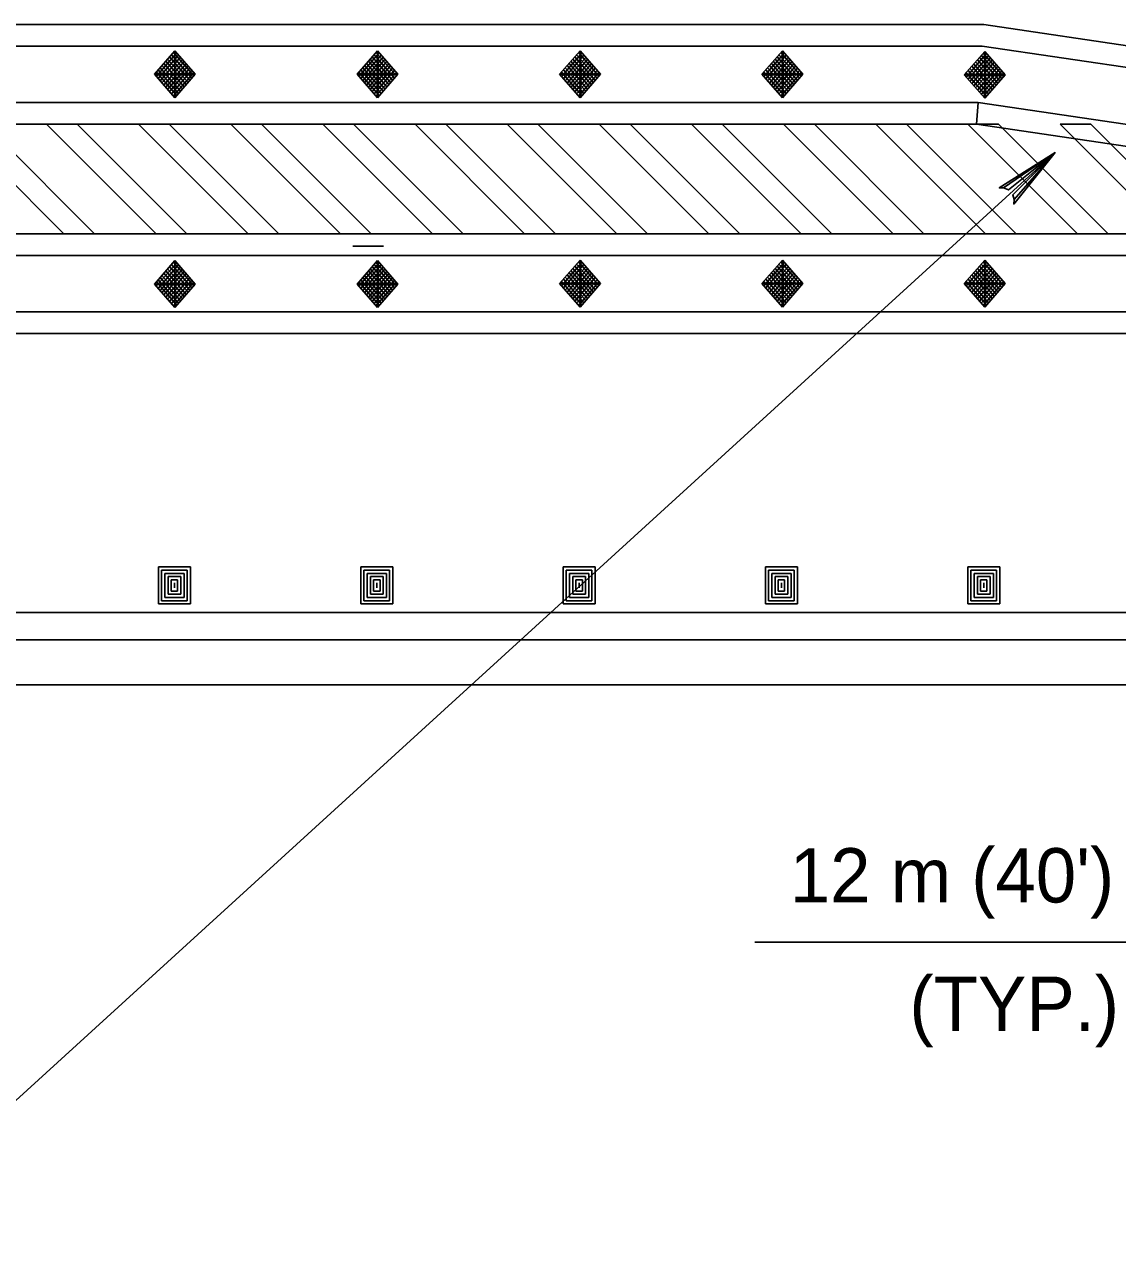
# Model space of a CAD drawing. Extents: x 639362 to 641108, y 298458 to 299646.
# Drawn here: x 639666.7 to 639727.1, y 298704.6 to 298772.2 of the extents above; entities that cross this region are included whole.
import ezdxf

# ---------------------------------------------------------------- set-up
doc = ezdxf.new("R2010")
doc.units = 0
doc.layers.add('2', color=7, linetype='Continuous')
doc.layers.add('3', color=7, linetype='Continuous')

# ---------------------------------------------------------------- blocks, each defined once
blk = doc.blocks.new('RARROW')
at = {"layer": '3'}
blk.add_lwpolyline([(-2.2695, 0.285), (-2.184875, 0.12075), (0, 0), (-2.2695, 0.285), (-2.38575, 0.384625), (0, 0), (-2.183125, -0.108), (-2.262875, -0.2705), (0, 0), (-2.38575, -0.379125), (-2.262875, -0.2705)], dxfattribs=at)

msp = doc.modelspace()

# ---------------------------------------------------------------- linework, layer by layer
at = {"layer": '2'}
for p, q in [((639719.726, 298772.157), (639431.255, 298772.157)), ((639797.996, 298760.59), (639719.726, 298772.157)), ((639431.255, 298770.957), (639719.637, 298770.957)), ((639675.014, 298770.702), (639673.887, 298769.407)), ((639675.119, 298770.582), (639674.005, 298769.303)), ((639675.223, 298770.462), (639674.095, 298769.167)), ((639674.826, 298770.486), (639675.954, 298769.191)), ((639674.931, 298770.606), (639676.058, 298769.311)), ((639676.142, 298769.407), (639675.014, 298770.702)), ((639675.014, 298770.702), (639675.014, 298768.111)), ((639686.213, 298770.702), (639685.085, 298769.407)), ((639686.317, 298770.582), (639685.204, 298769.303)), ((639686.421, 298770.462), (639685.294, 298769.167)), ((639686.025, 298770.486), (639687.152, 298769.191)), ((639686.129, 298770.606), (639687.257, 298769.311)), ((639687.34, 298769.407), (639686.213, 298770.702)), ((639686.213, 298770.702), (639686.213, 298768.111)), ((639697.412, 298770.696), (639696.284, 298769.401)), ((639697.516, 298770.576), (639696.403, 298769.298)), ((639697.224, 298770.48), (639698.351, 298769.185)), ((639697.328, 298770.6), (639698.456, 298769.305)), ((639698.539, 298769.401), (639697.412, 298770.696)), ((639697.412, 298770.696), (639697.412, 298768.106)), ((639708.595, 298770.696), (639707.468, 298769.401)), ((639708.7, 298770.576), (639707.587, 298769.298)), ((639708.408, 298770.48), (639709.535, 298769.185)), ((639708.512, 298770.6), (639709.639, 298769.305)), ((639709.723, 298769.401), (639708.595, 298770.696)), ((639708.595, 298770.696), (639708.595, 298768.106)), ((639719.779, 298770.666), (639718.652, 298769.371)), ((639719.884, 298770.547), (639718.77, 298769.268)), ((639719.637, 298770.957), (639797.908, 298759.39)), ((639719.696, 298770.57), (639720.823, 298769.275)), ((639720.907, 298769.371), (639719.779, 298770.666)), ((639719.779, 298770.666), (639719.779, 298768.076)), ((639675.327, 298770.342), (639674.2, 298769.047)), ((639675.432, 298770.223), (639674.304, 298768.927)), ((639674.304, 298769.887), (639675.432, 298768.591)), ((639675.536, 298770.103), (639674.409, 298768.807)), ((639674.409, 298770.007), (639675.536, 298768.711)), ((639674.513, 298770.127), (639675.641, 298768.831)), ((639675.641, 298769.983), (639674.513, 298768.687)), ((639674.617, 298770.247), (639675.745, 298768.951)), ((639675.745, 298769.863), (639674.617, 298768.567)), ((639674.722, 298770.366), (639675.849, 298769.071)), ((639686.526, 298770.342), (639685.398, 298769.047)), ((639686.63, 298770.223), (639685.503, 298768.927)), ((639685.503, 298769.887), (639686.63, 298768.591)), ((639686.735, 298770.103), (639685.607, 298768.807)), ((639685.607, 298770.007), (639686.735, 298768.711)), ((639685.711, 298770.127), (639686.839, 298768.831)), ((639686.839, 298769.983), (639685.711, 298768.687)), ((639685.816, 298770.247), (639686.943, 298768.951)), ((639686.943, 298769.863), (639685.816, 298768.567)), ((639685.92, 298770.366), (639687.048, 298769.071)), ((639697.621, 298770.456), (639696.493, 298769.161)), ((639697.725, 298770.337), (639696.597, 298769.041)), ((639697.829, 298770.217), (639696.702, 298768.921)), ((639696.702, 298769.881), (639697.829, 298768.585)), ((639697.934, 298770.097), (639696.806, 298768.801)), ((639696.806, 298770.001), (639697.934, 298768.705)), ((639696.911, 298770.121), (639698.038, 298768.825)), ((639698.038, 298769.977), (639696.911, 298768.681)), ((639697.015, 298770.241), (639698.143, 298768.945)), ((639698.143, 298769.857), (639697.015, 298768.561)), ((639697.119, 298770.361), (639698.247, 298769.065)), ((639708.804, 298770.456), (639707.677, 298769.161)), ((639708.909, 298770.337), (639707.781, 298769.041)), ((639709.013, 298770.217), (639707.885, 298768.921)), ((639707.885, 298769.881), (639709.013, 298768.585)), ((639709.117, 298770.097), (639707.99, 298768.801)), ((639707.99, 298770.001), (639709.117, 298768.705)), ((639708.094, 298770.121), (639709.222, 298768.825)), ((639709.222, 298769.977), (639708.094, 298768.681)), ((639708.199, 298770.241), (639709.326, 298768.945)), ((639709.326, 298769.857), (639708.199, 298768.561)), ((639708.303, 298770.361), (639709.431, 298769.065)), ((639719.988, 298770.427), (639718.86, 298769.131)), ((639720.092, 298770.307), (639718.965, 298769.011)), ((639720.197, 298770.187), (639719.069, 298768.891)), ((639719.069, 298769.851), (639720.197, 298768.555)), ((639720.301, 298770.067), (639719.174, 298768.771)), ((639719.174, 298769.971), (639720.301, 298768.675)), ((639719.278, 298770.091), (639720.406, 298768.795)), ((639720.406, 298769.947), (639719.278, 298768.651)), ((639719.382, 298770.211), (639720.51, 298768.915)), ((639720.51, 298769.827), (639719.382, 298768.531)), ((639719.487, 298770.331), (639720.614, 298769.035)), ((639719.591, 298770.451), (639720.719, 298769.155)), ((639673.887, 298769.407), (639675.014, 298768.111)), ((639673.887, 298769.407), (639676.142, 298769.407)), ((639673.991, 298769.527), (639675.119, 298768.231)), ((639674.095, 298769.647), (639675.223, 298768.351)), ((639674.2, 298769.767), (639675.327, 298768.471)), ((639675.849, 298769.743), (639674.722, 298768.447)), ((639675.954, 298769.623), (639674.826, 298768.327)), ((639676.058, 298769.503), (639674.931, 298768.207)), ((639675.014, 298768.111), (639676.142, 298769.407)), ((639685.085, 298769.407), (639686.213, 298768.111)), ((639685.085, 298769.407), (639687.34, 298769.407)), ((639685.189, 298769.527), (639686.317, 298768.231)), ((639685.294, 298769.647), (639686.421, 298768.351)), ((639685.398, 298769.767), (639686.526, 298768.471)), ((639687.048, 298769.743), (639685.92, 298768.447)), ((639687.152, 298769.623), (639686.025, 298768.327)), ((639687.257, 298769.503), (639686.129, 298768.207)), ((639686.213, 298768.111), (639687.34, 298769.407)), ((639696.284, 298769.401), (639697.412, 298768.106)), ((639696.284, 298769.401), (639698.539, 298769.401)), ((639696.389, 298769.521), (639697.516, 298768.225)), ((639696.493, 298769.641), (639697.621, 298768.345)), ((639696.597, 298769.761), (639697.725, 298768.465)), ((639698.247, 298769.737), (639697.119, 298768.441)), ((639698.351, 298769.617), (639697.224, 298768.321)), ((639698.456, 298769.497), (639697.328, 298768.201)), ((639697.412, 298768.106), (639698.539, 298769.401)), ((639707.468, 298769.401), (639708.595, 298768.106)), ((639707.468, 298769.401), (639709.723, 298769.401)), ((639707.572, 298769.521), (639708.7, 298768.225)), ((639707.677, 298769.641), (639708.804, 298768.345)), ((639707.781, 298769.761), (639708.909, 298768.465)), ((639709.431, 298769.737), (639708.303, 298768.441)), ((639709.535, 298769.617), (639708.408, 298768.321)), ((639709.639, 298769.497), (639708.512, 298768.201)), ((639708.595, 298768.106), (639709.723, 298769.401)), ((639718.652, 298769.371), (639719.779, 298768.076)), ((639718.652, 298769.371), (639720.907, 298769.371)), ((639718.756, 298769.491), (639719.884, 298768.196)), ((639718.86, 298769.611), (639719.988, 298768.315)), ((639718.965, 298769.731), (639720.092, 298768.435)), ((639720.614, 298769.707), (639719.487, 298768.411)), ((639720.719, 298769.587), (639719.591, 298768.292)), ((639720.823, 298769.467), (639719.696, 298768.172)), ((639719.779, 298768.076), (639720.907, 298769.371)), ((639719.409, 298767.845), (639606.893, 298767.845)), ((639719.409, 298767.845), (639719.32, 298766.645)), ((639719.32, 298766.645), (639719.409, 298767.845)), ((639776.623, 298759.39), (639719.409, 298767.845)), ((639623.223, 298766.645), (639719.32, 298766.645)), ((639668.883, 298760.59), (639662.822, 298766.645)), ((639664.52, 298766.645), (639670.58, 298760.59)), ((639673.976, 298760.59), (639667.916, 298766.645)), ((639667.916, 298766.645), (639669.614, 298766.645)), ((639669.614, 298766.645), (639675.674, 298760.59)), ((639679.07, 298760.59), (639673.009, 298766.645)), ((639673.009, 298766.645), (639674.707, 298766.645)), ((639674.707, 298766.645), (639680.767, 298760.59)), ((639684.163, 298760.59), (639678.103, 298766.645)), ((639678.103, 298766.645), (639679.801, 298766.645)), ((639679.801, 298766.645), (639685.861, 298760.59)), ((639689.257, 298760.59), (639683.196, 298766.645)), ((639683.196, 298766.645), (639684.894, 298766.645)), ((639684.894, 298766.645), (639690.954, 298760.59)), ((639694.35, 298760.59), (639688.29, 298766.645)), ((639688.29, 298766.645), (639689.988, 298766.645)), ((639689.988, 298766.645), (639696.048, 298760.59)), ((639699.444, 298760.59), (639693.383, 298766.645)), ((639693.383, 298766.645), (639695.081, 298766.645)), ((639695.081, 298766.645), (639701.141, 298760.59)), ((639704.537, 298760.59), (639698.477, 298766.645)), ((639698.477, 298766.645), (639700.175, 298766.645)), ((639700.175, 298766.645), (639706.235, 298760.59)), ((639709.631, 298760.59), (639703.57, 298766.645)), ((639703.57, 298766.645), (639705.268, 298766.645)), ((639705.268, 298766.645), (639711.328, 298760.59)), ((639714.724, 298760.59), (639708.664, 298766.645)), ((639708.664, 298766.645), (639710.362, 298766.645)), ((639710.362, 298766.645), (639716.422, 298760.59)), ((639719.818, 298760.59), (639713.757, 298766.645)), ((639713.757, 298766.645), (639715.455, 298766.645)), ((639715.455, 298766.645), (639721.515, 298760.59)), ((639724.911, 298760.59), (639718.851, 298766.645)), ((639718.851, 298766.645), (639720.549, 298766.645)), ((639719.32, 298766.645), (639760.294, 298760.59)), ((639720.549, 298766.645), (639726.609, 298760.59)), ((639730.005, 298760.59), (639723.944, 298766.645)), ((639723.944, 298766.645), (639725.642, 298766.645)), ((639725.642, 298766.645), (639731.702, 298760.59)), ((639657.3, 298704.573), (639723.666, 298765.08)), ((639760.294, 298760.59), (639664.196, 298760.59)), ((639670.58, 298760.59), (639668.883, 298760.59)), ((639675.674, 298760.59), (639673.976, 298760.59)), ((639680.767, 298760.59), (639679.07, 298760.59)), ((639685.861, 298760.59), (639684.163, 298760.59)), ((639690.954, 298760.59), (639689.257, 298760.59)), ((639696.048, 298760.59), (639694.35, 298760.59)), ((639701.141, 298760.59), (639699.444, 298760.59)), ((639706.235, 298760.59), (639704.537, 298760.59)), ((639711.328, 298760.59), (639709.631, 298760.59)), ((639716.422, 298760.59), (639714.724, 298760.59)), ((639721.515, 298760.59), (639719.818, 298760.59)), ((639726.609, 298760.59), (639724.911, 298760.59)), ((639686.547, 298759.905), (639684.849, 298759.905)), ((639664.108, 298759.39), (639776.623, 298759.39)), ((639675.014, 298759.11), (639673.887, 298757.814)), ((639675.119, 298758.99), (639674.005, 298757.711)), ((639674.931, 298759.014), (639676.058, 298757.718)), ((639676.142, 298757.814), (639675.014, 298759.11)), ((639675.014, 298759.11), (639675.014, 298756.519)), ((639686.213, 298759.11), (639685.085, 298757.814)), ((639686.317, 298758.99), (639685.204, 298757.711)), ((639686.129, 298759.014), (639687.257, 298757.718)), ((639687.34, 298757.814), (639686.213, 298759.11)), ((639686.213, 298759.11), (639686.213, 298756.519)), ((639697.412, 298759.13), (639696.284, 298757.835)), ((639697.516, 298759.01), (639696.403, 298757.731)), ((639697.328, 298759.034), (639698.456, 298757.739)), ((639698.539, 298757.835), (639697.412, 298759.13)), ((639697.412, 298759.13), (639697.412, 298756.539)), ((639708.595, 298759.13), (639707.468, 298757.835)), ((639708.7, 298759.01), (639707.587, 298757.731)), ((639708.512, 298759.034), (639709.639, 298757.739)), ((639709.723, 298757.835), (639708.595, 298759.13)), ((639708.595, 298759.13), (639708.595, 298756.539)), ((639719.779, 298759.13), (639718.652, 298757.835)), ((639719.884, 298759.01), (639718.77, 298757.731)), ((639719.696, 298759.034), (639720.823, 298757.739)), ((639720.907, 298757.835), (639719.779, 298759.13)), ((639719.779, 298759.13), (639719.779, 298756.539)), ((639675.223, 298758.87), (639674.095, 298757.574)), ((639675.327, 298758.75), (639674.2, 298757.454)), ((639675.432, 298758.63), (639674.304, 298757.335)), ((639674.304, 298758.294), (639675.432, 298756.999)), ((639675.536, 298758.51), (639674.409, 298757.215)), ((639674.409, 298758.414), (639675.536, 298757.119)), ((639674.513, 298758.534), (639675.641, 298757.239)), ((639675.641, 298758.39), (639674.513, 298757.095)), ((639674.617, 298758.654), (639675.745, 298757.359)), ((639674.722, 298758.774), (639675.849, 298757.478)), ((639674.826, 298758.894), (639675.954, 298757.598)), ((639686.421, 298758.87), (639685.294, 298757.574)), ((639686.526, 298758.75), (639685.398, 298757.454)), ((639686.63, 298758.63), (639685.503, 298757.335)), ((639685.503, 298758.294), (639686.63, 298756.999)), ((639686.735, 298758.51), (639685.607, 298757.215)), ((639685.607, 298758.414), (639686.735, 298757.119)), ((639685.711, 298758.534), (639686.839, 298757.239)), ((639686.839, 298758.39), (639685.711, 298757.095)), ((639685.816, 298758.654), (639686.943, 298757.359)), ((639685.92, 298758.774), (639687.048, 298757.478)), ((639686.025, 298758.894), (639687.152, 298757.598)), ((639697.621, 298758.89), (639696.493, 298757.595)), ((639697.725, 298758.77), (639696.597, 298757.475)), ((639697.829, 298758.65), (639696.702, 298757.355)), ((639696.702, 298758.314), (639697.829, 298757.019)), ((639697.934, 298758.53), (639696.806, 298757.235)), ((639696.806, 298758.434), (639697.934, 298757.139)), ((639696.911, 298758.554), (639698.038, 298757.259)), ((639698.038, 298758.41), (639696.911, 298757.115)), ((639697.015, 298758.674), (639698.143, 298757.379)), ((639697.119, 298758.794), (639698.247, 298757.499)), ((639697.224, 298758.914), (639698.351, 298757.619)), ((639708.804, 298758.89), (639707.677, 298757.595)), ((639708.909, 298758.77), (639707.781, 298757.475)), ((639709.013, 298758.65), (639707.885, 298757.355)), ((639707.885, 298758.314), (639709.013, 298757.019)), ((639709.117, 298758.53), (639707.99, 298757.235)), ((639707.99, 298758.434), (639709.117, 298757.139)), ((639708.094, 298758.554), (639709.222, 298757.259)), ((639709.222, 298758.41), (639708.094, 298757.115)), ((639708.199, 298758.674), (639709.326, 298757.379)), ((639708.303, 298758.794), (639709.431, 298757.499)), ((639708.408, 298758.914), (639709.535, 298757.619)), ((639719.988, 298758.89), (639718.86, 298757.595)), ((639720.092, 298758.77), (639718.965, 298757.475)), ((639720.197, 298758.65), (639719.069, 298757.355)), ((639719.069, 298758.314), (639720.197, 298757.019)), ((639720.301, 298758.53), (639719.174, 298757.235)), ((639719.174, 298758.434), (639720.301, 298757.139)), ((639719.278, 298758.554), (639720.406, 298757.259)), ((639720.406, 298758.41), (639719.278, 298757.115)), ((639719.382, 298758.674), (639720.51, 298757.379)), ((639719.487, 298758.794), (639720.614, 298757.499)), ((639719.591, 298758.914), (639720.719, 298757.619)), ((639673.887, 298757.814), (639675.014, 298756.519)), ((639673.887, 298757.814), (639676.142, 298757.814)), ((639673.991, 298757.934), (639675.119, 298756.639)), ((639674.095, 298758.054), (639675.223, 298756.759)), ((639674.2, 298758.174), (639675.327, 298756.879)), ((639675.745, 298758.27), (639674.617, 298756.975)), ((639675.849, 298758.15), (639674.722, 298756.855)), ((639675.954, 298758.03), (639674.826, 298756.735)), ((639676.058, 298757.91), (639674.931, 298756.615)), ((639675.014, 298756.519), (639676.142, 298757.814)), ((639685.085, 298757.814), (639686.213, 298756.519)), ((639685.085, 298757.814), (639687.34, 298757.814)), ((639685.189, 298757.934), (639686.317, 298756.639)), ((639685.294, 298758.054), (639686.421, 298756.759)), ((639685.398, 298758.174), (639686.526, 298756.879)), ((639686.943, 298758.27), (639685.816, 298756.975)), ((639687.048, 298758.15), (639685.92, 298756.855)), ((639687.152, 298758.03), (639686.025, 298756.735)), ((639687.257, 298757.91), (639686.129, 298756.615)), ((639686.213, 298756.519), (639687.34, 298757.814)), ((639696.284, 298757.835), (639697.412, 298756.539)), ((639696.284, 298757.835), (639698.539, 298757.835)), ((639696.389, 298757.955), (639697.516, 298756.659)), ((639696.493, 298758.075), (639697.621, 298756.779)), ((639696.597, 298758.194), (639697.725, 298756.899)), ((639698.143, 298758.29), (639697.015, 298756.995)), ((639698.247, 298758.17), (639697.119, 298756.875)), ((639698.351, 298758.051), (639697.224, 298756.755)), ((639698.456, 298757.931), (639697.328, 298756.635)), ((639697.412, 298756.539), (639698.539, 298757.835)), ((639707.468, 298757.835), (639708.595, 298756.539)), ((639707.468, 298757.835), (639709.723, 298757.835)), ((639707.572, 298757.955), (639708.7, 298756.659)), ((639707.677, 298758.075), (639708.804, 298756.779)), ((639707.781, 298758.194), (639708.909, 298756.899)), ((639709.326, 298758.29), (639708.199, 298756.995)), ((639709.431, 298758.17), (639708.303, 298756.875)), ((639709.535, 298758.051), (639708.408, 298756.755)), ((639709.639, 298757.931), (639708.512, 298756.635)), ((639708.595, 298756.539), (639709.723, 298757.835)), ((639718.652, 298757.835), (639719.779, 298756.539)), ((639718.652, 298757.835), (639720.907, 298757.835)), ((639718.756, 298757.955), (639719.884, 298756.659)), ((639718.86, 298758.075), (639719.988, 298756.779)), ((639718.965, 298758.194), (639720.092, 298756.899)), ((639720.51, 298758.29), (639719.382, 298756.995)), ((639720.614, 298758.17), (639719.487, 298756.875)), ((639720.719, 298758.051), (639719.591, 298756.755)), ((639720.823, 298757.931), (639719.696, 298756.635)), ((639719.779, 298756.539), (639720.907, 298757.835)), ((639663.879, 298756.279), (639952.262, 298756.279)), ((639952.262, 298755.079), (639663.791, 298755.079)), ((639674.106, 298742.179), (639675.881, 298742.179)), ((639674.106, 298740.14), (639674.106, 298742.179)), ((639675.881, 298742.179), (639675.881, 298740.14)), ((639685.289, 298742.179), (639687.064, 298742.179)), ((639685.289, 298740.14), (639685.289, 298742.179)), ((639687.064, 298742.179), (639687.064, 298740.14)), ((639696.473, 298742.179), (639698.248, 298742.179)), ((639696.473, 298740.14), (639696.473, 298742.179)), ((639698.248, 298742.179), (639698.248, 298740.14)), ((639707.657, 298742.179), (639709.432, 298742.179)), ((639707.657, 298740.14), (639707.657, 298742.179)), ((639709.432, 298742.179), (639709.432, 298740.14)), ((639718.841, 298742.179), (639720.616, 298742.179)), ((639718.841, 298740.14), (639718.841, 298742.179)), ((639720.616, 298742.179), (639720.616, 298740.14)), ((639674.283, 298742.001), (639675.702, 298742.001)), ((639674.283, 298740.317), (639674.283, 298742.001)), ((639674.461, 298741.824), (639675.525, 298741.824)), ((639674.461, 298740.495), (639674.461, 298741.824)), ((639674.638, 298740.672), (639674.638, 298741.647)), ((639674.638, 298741.647), (639675.347, 298741.647)), ((639674.816, 298741.471), (639675.17, 298741.471)), ((639674.816, 298740.849), (639674.816, 298741.471)), ((639675.17, 298741.471), (639675.17, 298740.849)), ((639675.347, 298741.647), (639675.347, 298740.672)), ((639675.525, 298741.824), (639675.525, 298740.495)), ((639675.702, 298742.001), (639675.702, 298740.317)), ((639685.466, 298742.001), (639686.886, 298742.001)), ((639685.466, 298740.317), (639685.466, 298742.001)), ((639685.645, 298741.824), (639686.709, 298741.824)), ((639685.645, 298740.495), (639685.645, 298741.824)), ((639685.822, 298740.672), (639685.822, 298741.647)), ((639685.822, 298741.647), (639686.531, 298741.647)), ((639686, 298741.471), (639686.354, 298741.471)), ((639686, 298740.849), (639686, 298741.471)), ((639686.354, 298741.471), (639686.354, 298740.849)), ((639686.531, 298741.647), (639686.531, 298740.672)), ((639686.709, 298741.824), (639686.709, 298740.495)), ((639686.886, 298742.001), (639686.886, 298740.317)), ((639696.65, 298742.001), (639698.07, 298742.001)), ((639696.65, 298740.317), (639696.65, 298742.001)), ((639696.829, 298741.824), (639697.893, 298741.824)), ((639696.829, 298740.495), (639696.829, 298741.824)), ((639697.005, 298740.672), (639697.005, 298741.647)), ((639697.005, 298741.647), (639697.715, 298741.647)), ((639697.184, 298741.471), (639697.538, 298741.471)), ((639697.184, 298740.849), (639697.184, 298741.471)), ((639697.538, 298741.471), (639697.538, 298740.849)), ((639697.715, 298741.647), (639697.715, 298740.672)), ((639697.893, 298741.824), (639697.893, 298740.495)), ((639698.07, 298742.001), (639698.07, 298740.317)), ((639707.834, 298742.001), (639709.254, 298742.001)), ((639707.834, 298740.317), (639707.834, 298742.001)), ((639708.012, 298741.824), (639709.077, 298741.824)), ((639708.012, 298740.495), (639708.012, 298741.824)), ((639708.189, 298740.672), (639708.189, 298741.647)), ((639708.189, 298741.647), (639708.898, 298741.647)), ((639708.367, 298741.471), (639708.721, 298741.471)), ((639708.367, 298740.849), (639708.367, 298741.471)), ((639708.721, 298741.471), (639708.721, 298740.849)), ((639708.898, 298741.647), (639708.898, 298740.672)), ((639709.077, 298741.824), (639709.077, 298740.495)), ((639709.254, 298742.001), (639709.254, 298740.317)), ((639719.018, 298742.001), (639720.437, 298742.001)), ((639719.018, 298740.317), (639719.018, 298742.001)), ((639719.196, 298741.824), (639720.26, 298741.824)), ((639719.196, 298740.495), (639719.196, 298741.824)), ((639719.373, 298740.672), (639719.373, 298741.647)), ((639719.373, 298741.647), (639720.082, 298741.647)), ((639719.551, 298741.471), (639719.905, 298741.471)), ((639719.551, 298740.849), (639719.551, 298741.471)), ((639719.905, 298741.471), (639719.905, 298740.849)), ((639720.082, 298741.647), (639720.082, 298740.672)), ((639720.26, 298741.824), (639720.26, 298740.495)), ((639720.437, 298742.001), (639720.437, 298740.317)), ((639675.17, 298740.849), (639674.816, 298740.849)), ((639674.99, 298741.294), (639674.99, 298741.026)), ((639686.354, 298740.849), (639686, 298740.849)), ((639686.174, 298741.294), (639686.174, 298741.026)), ((639697.538, 298740.849), (639697.184, 298740.849)), ((639697.358, 298741.294), (639697.358, 298741.026)), ((639708.721, 298740.849), (639708.367, 298740.849)), ((639708.542, 298741.294), (639708.542, 298741.026)), ((639719.905, 298740.849), (639719.551, 298740.849)), ((639719.726, 298741.294), (639719.726, 298741.026)), ((639675.881, 298740.14), (639674.106, 298740.14)), ((639675.702, 298740.317), (639674.283, 298740.317)), ((639675.525, 298740.495), (639674.461, 298740.495)), ((639675.347, 298740.672), (639674.638, 298740.672)), ((639687.064, 298740.14), (639685.289, 298740.14)), ((639686.886, 298740.317), (639685.466, 298740.317)), ((639686.709, 298740.495), (639685.645, 298740.495)), ((639686.531, 298740.672), (639685.822, 298740.672)), ((639698.248, 298740.14), (639696.473, 298740.14)), ((639698.07, 298740.317), (639696.65, 298740.317)), ((639697.893, 298740.495), (639696.829, 298740.495)), ((639697.715, 298740.672), (639697.005, 298740.672)), ((639709.432, 298740.14), (639707.657, 298740.14)), ((639709.254, 298740.317), (639707.834, 298740.317)), ((639709.077, 298740.495), (639708.012, 298740.495)), ((639708.898, 298740.672), (639708.189, 298740.672)), ((639720.616, 298740.14), (639718.841, 298740.14)), ((639720.437, 298740.317), (639719.018, 298740.317)), ((639720.26, 298740.495), (639719.196, 298740.495)), ((639720.082, 298740.672), (639719.373, 298740.672)), ((639431.348, 298739.66), (639952.736, 298739.66)), ((639431.348, 298738.16), (639952.736, 298738.16)), ((639431.348, 298735.66), (639952.736, 298735.66)), ((639707.067, 298721.456), (639742.105, 298721.456))]:
    msp.add_line(p, q, dxfattribs=at)

# ---------------------------------------------------------------- block references
at = {"layer": '2', "xscale": 1.5089217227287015, "yscale": 1.5711553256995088, "rotation": 41.96912032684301}
msp.add_blockref('RARROW', (639723.666, 298765.08), dxfattribs=at)

# ---------------------------------------------------------------- texts
at = {"layer": '2'}
for s, p in [("12 m (40')", (639709.003, 298723.64)), ('(TYP.)', (639715.617, 298716.544))]:
    msp.add_text(s, height=3, dxfattribs=at).set_placement(p)

doc.saveas('drawing.dxf')
